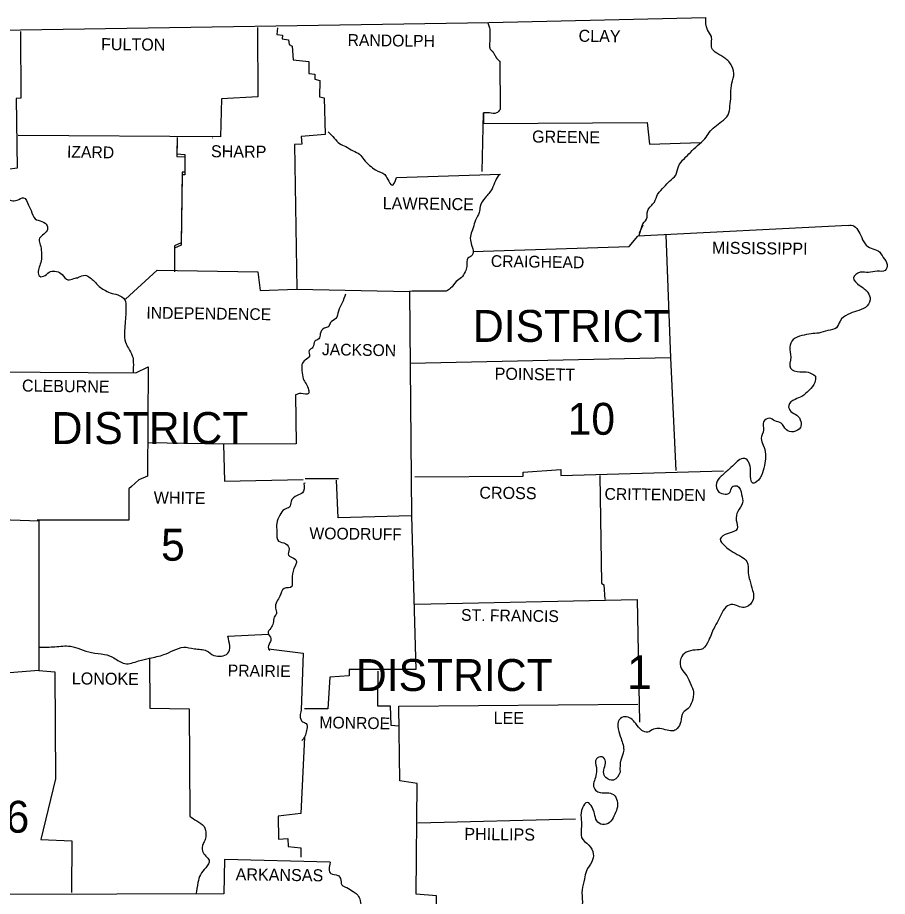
# Model space of a CAD drawing. Extents: x 1334737.7 to 1334827.2, y 402732.3 to 402753.5.
# Drawn here: x 1334823.697 to 1334827.213, y 402749.977 to 402753.53 of the extents above; entities that cross this region are included whole.
import ezdxf

# ---------------------------------------------------------------- set-up
doc = ezdxf.new("R2010")
doc.units = 0
doc.layers.add('Default', color=7, linetype='Continuous')

msp = doc.modelspace()

# ---------------------------------------------------------------- linework, layer by layer
at = {"layer": 'Default'}
for p, q in [((1334825.6459, 402753.3538), (1334825.6479, 402753.1584)), ((1334826.2084, 402752.6464), (1334826.2217, 402752.6885)), ((1334826.2114, 402752.6597), (1334826.2258, 402752.6926)), ((1334824.8603, 402751.6664), (1334824.995, 402751.6664))]:
    msp.add_line(p, q, dxfattribs=at)
for points in [[(1334820.2741, 402753.4772), (1334822.1034, 402753.4762), (1334823.7086, 402753.4803), (1334825.6027, 402753.5091), (1334826.4798, 402753.5297)], [(1334824.6669, 402753.4895), (1334824.669, 402753.2099), (1334824.522, 402753.2016), (1334824.5178, 402753.0474), (1334823.6993, 402753.0525)], [(1334824.7482, 402753.4885), (1334824.7451, 402753.4618), (1334824.7677, 402753.4587), (1334824.7667, 402753.4443), (1334824.7924, 402753.4392), (1334824.7945, 402753.4207), (1334824.8068, 402753.4135), (1334824.8109, 402753.359), (1334824.8747, 402753.3518), (1334824.8747, 402753.3034), (1334824.8983, 402753.3003), (1334824.8983, 402753.2808), (1334824.9189, 402753.2757), (1334824.9178, 402753.2099), (1334824.9364, 402753.2057), (1334824.9405, 402753.0577), (1334824.8438, 402753.0494), (1334824.8459, 402753.0176), (1334824.816, 402753.0165), (1334824.8263, 402752.4325), (1334825.2819, 402752.4222), (1334825.2901, 402751.5152), (1334824.9929, 402751.507), (1334824.9867, 402751.6602)], [(1334823.7086, 402753.4731), (1334823.7106, 402753.2037), (1334823.6921, 402753.2027), (1334823.6952, 402752.9209), (1334823.616, 402752.9096), (1334823.6222, 402752.8335), (1334823.65, 402752.7985), (1334823.6479, 402752.7101), (1334823.4937, 402752.7039), (1334823.4885, 402752.5661), (1334823.3477, 402752.561), (1334823.3415, 402752.3944), (1334823.3487, 402752.38), (1334823.3528, 402752.1137), (1334823.5944, 402752.0972), (1334823.5914, 402751.5019), (1334823.7836, 402751.4957), (1334823.7836, 402750.89), (1334823.6315, 402750.8787), (1334823.6201, 402750.745), (1334823.3662, 402750.744)], [(1334825.5749, 402752.9075), (1334825.5811, 402753.144), (1334825.5811, 402753.1019), (1334826.2423, 402753.105), (1334826.2515, 402753.0176), (1334826.4588, 402753.0244)], [(1334824.343, 402753.0443), (1334824.341, 402752.9785), (1334824.3729, 402752.9764), (1334824.3739, 402752.9045), (1334824.3626, 402752.9045), (1334824.3585, 402752.6196), (1334824.3317, 402752.6073), (1334824.3317, 402752.5127)], [(1334824.343, 402753.034), (1334824.341, 402752.9682), (1334824.3729, 402752.9662), (1334824.3739, 402752.8942), (1334824.3626, 402752.8942), (1334824.3585, 402752.6093), (1334824.3317, 402752.598), (1334824.3317, 402752.5024)], [(1334824.4849, 402753.0422), (1334824.486, 402753.0433)], [(1334825.2284, 402752.8829), (1334825.649, 402752.8973)], [(1334827.0546, 402752.6895), (1334826.2049, 402752.6458)], [(1334825.5376, 402752.5835), (1334826.1693, 402752.6042), (1334826.2049, 402752.6458)], [(1334826.3171, 402752.6516), (1334826.3359, 402752.1548), (1334826.3585, 402751.6993)], [(1334824.1333, 402752.3913), (1334824.2618, 402752.5086), (1334824.669, 402752.5024), (1334824.6772, 402752.4263), (1334824.8253, 402752.4325)], [(1334825.4299, 402752.4242), (1334825.2921, 402752.4242), (1334825.2819, 402752.4222)], [(1334826.3359, 402752.1548), (1334825.2845, 402752.131)], [(1334823.5944, 402752.0972), (1334824.1754, 402752.0942), (1334824.2258, 402752.1178), (1334824.2227, 402751.6756), (1334824.1878, 402751.6613), (1334824.1579, 402751.6345), (1334824.1477, 402751.6253), (1334824.1466, 402751.4978), (1334823.7764, 402751.4978)], [(1334824.8202, 402752.0047), (1334824.8232, 402751.8062), (1334824.5292, 402751.8052), (1334824.2268, 402751.8104)], [(1334824.5292, 402751.8052), (1334824.5333, 402751.6561), (1334824.851, 402751.6623)], [(1334825.3035, 402751.6736), (1334825.7405, 402751.6756), (1334825.7415, 402751.6921), (1334825.8927, 402751.7024), (1334825.8927, 402751.6787), (1334826.5508, 402751.6972)], [(1334826.051, 402751.6787), (1334826.0572, 402751.2438), (1334826.0675, 402751.2366), (1334826.0706, 402751.178)], [(1334824.8603, 402751.6479), (1334824.8541, 402751.6469)], [(1334825.2901, 402751.5152), (1334825.3065, 402750.8952), (1334825.0382, 402750.8941), (1334825.0371, 402750.8695), (1334824.959, 402750.8643), (1334824.9518, 402750.7358), (1334824.8572, 402750.7358)], [(1334825.3035, 402751.1584), (1334826.2012, 402751.1769)], [(1334826.2012, 402751.1769), (1334826.2104, 402750.6813)], [(1334824.5466, 402751.0299), (1334824.7112, 402751.0381)], [(1334824.7112, 402750.9785), (1334824.852, 402750.961), (1334824.8438, 402750.7296)], [(1334824.2299, 402750.9415), (1334824.232, 402750.7389), (1334824.3914, 402750.7358), (1334824.3934, 402750.3019)], [(1334823.7836, 402750.89), (1334823.8484, 402750.8849), (1334823.8505, 402750.453), (1334823.7908, 402750.2073), (1334823.9163, 402750.2021), (1334823.9153, 402749.9934)], [(1334825.1533, 402750.888), (1334825.1523, 402750.7481), (1334825.2037, 402750.7481), (1334825.2058, 402750.67), (1334825.2387, 402750.6669)], [(1334825.3035, 402749.7445), (1334825.3919, 402749.7507), (1334825.3909, 402749.98), (1334825.3086, 402749.9862), (1334825.3127, 402750.4345), (1334825.2418, 402750.4448), (1334825.2387, 402750.7471), (1334826.2042, 402750.7543)], [(1334824.8572, 402750.6217), (1334824.8428, 402750.3121), (1334824.7502, 402750.3019), (1334824.7523, 402750.2093), (1334824.7903, 402750.2114), (1334824.7914, 402750.1795), (1334824.8418, 402750.1733), (1334824.8428, 402750.1363)], [(1334825.3148, 402750.2751), (1334825.9523, 402750.2916)], [(1334824.961, 402750.1157), (1334824.5333, 402750.127), (1334824.5312, 402749.9882), (1334823.6654, 402749.9851)]]:
    msp.add_lwpolyline(points, dxfattribs=at)
for points in [[(1334826.2207, 402752.6834), (1334826.2217, 402752.6885), (1334826.2392, 402752.7152), (1334826.2443, 402752.7492), (1334826.2711, 402752.7841), (1334826.2844, 402752.815), (1334826.3112, 402752.8458), (1334826.3317, 402752.8685), (1334826.3575, 402752.8931), (1334826.3688, 402752.9281), (1334826.3924, 402752.96), (1334826.4171, 402752.9847), (1334826.4459, 402753.0124), (1334826.4757, 402753.0402), (1334826.4922, 402753.0649), (1334826.5158, 402753.0885), (1334826.5425, 402753.1091), (1334826.5693, 402753.1368), (1334826.5765, 402753.1718), (1334826.5806, 402753.2109), (1334826.5826, 402753.2551), (1334826.5919, 402753.2942), (1334826.5847, 402753.3332), (1334826.5559, 402753.3662), (1334826.523, 402753.3857), (1334826.5035, 402753.4063), (1334826.5014, 402753.4536), (1334826.486, 402753.4803), (1334826.4798, 402753.5297)], [(1334825.5966, 402753.509), (1334825.5992, 402753.5039), (1334825.6047, 402753.4879), (1334825.6064, 402753.477), (1334825.6067, 402753.4715), (1334825.6068, 402753.4659), (1334825.6066, 402753.4584), (1334825.6063, 402753.451), (1334825.606, 402753.4435), (1334825.6058, 402753.4361), (1334825.6057, 402753.4325), (1334825.6052, 402753.4217), (1334825.6052, 402753.4145), (1334825.6054, 402753.4109), (1334825.6055, 402753.4091), (1334825.6056, 402753.4082), (1334825.6058, 402753.4073), (1334825.6079, 402753.402), (1334825.6118, 402753.3975), (1334825.6163, 402753.3933), (1334825.6184, 402753.3911), (1334825.6202, 402753.3888), (1334825.6238, 402753.3827), (1334825.6271, 402753.3764), (1334825.6306, 402753.3701), (1334825.6325, 402753.3671), (1334825.6346, 402753.3641), (1334825.637, 402753.3612), (1334825.6397, 402753.3586), (1334825.6427, 402753.3562), (1334825.6459, 402753.3538)], [(1334825.6479, 402753.1584), (1334825.6325, 402753.144), (1334825.6047, 402753.144), (1334825.5811, 402753.144)], [(1334824.9528, 402753.068), (1334824.9775, 402753.0422), (1334824.9991, 402753.0206), (1334825.0238, 402753.0083), (1334825.0536, 402752.9908), (1334825.0793, 402752.9775), (1334825.0968, 402752.9559), (1334825.1204, 402752.9322), (1334825.1441, 402752.9137), (1334825.1811, 402752.8952), (1334825.1934, 402752.8757), (1334825.2109, 402752.852), (1334825.2284, 402752.8829)], [(1334825.6448, 402752.8962), (1334825.6284, 402752.8695), (1334825.615, 402752.8376), (1334825.5873, 402752.8016), (1334825.5667, 402752.7656), (1334825.5636, 402752.742), (1334825.5482, 402752.7111), (1334825.5389, 402752.6793), (1334825.5287, 402752.6515), (1334825.5287, 402752.6237), (1334825.5369, 402752.5949), (1334825.5348, 402752.5692), (1334825.5173, 402752.5569), (1334825.5132, 402752.524), (1334825.506, 402752.5014), (1334825.4916, 402752.4787), (1334825.47, 402752.4623), (1334825.4474, 402752.4356), (1334825.4299, 402752.4242)], [(1334823.65, 402752.7985), (1334823.6952, 402752.7913), (1334823.7219, 402752.8016), (1334823.7415, 402752.7718), (1334823.7518, 402752.7492), (1334823.7682, 402752.7163), (1334823.796, 402752.706), (1334823.8166, 402752.6885), (1334823.8166, 402752.669), (1334823.798, 402752.6505), (1334823.7847, 402752.633), (1334823.7888, 402752.6114), (1334823.7939, 402752.5816), (1334823.7939, 402752.5538), (1334823.7867, 402752.5271), (1334823.7806, 402752.5034), (1334823.7867, 402752.4839), (1334823.8083, 402752.487), (1334823.8309, 402752.5034), (1334823.8546, 402752.5034), (1334823.8772, 402752.4911), (1334823.9009, 402752.4695), (1334823.9245, 402752.4746), (1334823.9441, 402752.4798), (1334823.9708, 402752.488), (1334823.9903, 402752.4777), (1334824.0068, 402752.4643), (1334824.0273, 402752.4428), (1334824.0469, 402752.4294), (1334824.0716, 402752.417), (1334824.1024, 402752.4088), (1334824.1302, 402752.3893), (1334824.1353, 402752.3564), (1334824.1343, 402752.3286), (1334824.1322, 402752.2936), (1334824.1292, 402752.2546), (1334824.1333, 402752.2176), (1334824.1456, 402752.1929), (1334824.161, 402752.1631), (1334824.1651, 402752.1363), (1334824.1641, 402752.0931)], [(1334827.0546, 402752.6895), (1334827.067, 402752.6906), (1334827.105, 402752.6494), (1334827.1225, 402752.6155), (1334827.1472, 402752.597), (1334827.176, 402752.5867), (1334827.1965, 402752.56), (1334827.212, 402752.5322), (1334827.2037, 402752.5075), (1334827.1719, 402752.5044), (1334827.1369, 402752.4993), (1334827.103, 402752.5003), (1334827.0762, 402752.4777), (1334827.1009, 402752.4469), (1334827.1338, 402752.4191), (1334827.1431, 402752.3883), (1334827.1246, 402752.3584), (1334827.0886, 402752.343), (1334827.0536, 402752.3296), (1334827.0217, 402752.3029), (1334827.0073, 402752.2762), (1334826.9724, 402752.2649), (1334826.9354, 402752.2546), (1334826.9045, 402752.2515), (1334826.8675, 402752.2443), (1334826.8325, 402752.2278), (1334826.8181, 402752.198), (1334826.8222, 402752.1569), (1334826.8212, 402752.1127), (1334826.8593, 402752.0972), (1334826.8922, 402752.0962), (1334826.923, 402752.0798)], [(1334825.0227, 402752.4119), (1334825.0094, 402752.3769), (1334824.9939, 402752.343), (1334824.9837, 402752.3132), (1334824.9621, 402752.2967), (1334824.9549, 402752.2813), (1334824.9364, 402752.2741), (1334824.9209, 402752.2515), (1334824.9148, 402752.2309), (1334824.8983, 402752.2217), (1334824.8911, 402752.197), (1334824.8757, 402752.1836), (1334824.8767, 402752.161), (1334824.8603, 402752.1456), (1334824.8469, 402752.1271), (1334824.8469, 402752.1024), (1334824.852, 402752.0695), (1334824.8633, 402752.0499), (1334824.8736, 402752.0253), (1334824.8726, 402752.0098), (1334824.8438, 402752.0098), (1334824.8202, 402752.0047)], [(1334826.923, 402752.0798), (1334826.9199, 402752.0551), (1334826.8963, 402752.0232), (1334826.8675, 402751.9985), (1334826.8397, 402751.9862), (1334826.814, 402751.9615), (1334826.8222, 402751.9379), (1334826.8469, 402751.9224), (1334826.8634, 402751.8967), (1334826.8613, 402751.8731), (1334826.8335, 402751.8556), (1334826.8048, 402751.8628), (1334826.7832, 402751.8906), (1334826.7585, 402751.8998), (1334826.7369, 402751.9101), (1334826.7122, 402751.8957), (1334826.7122, 402751.8628), (1334826.703, 402751.8278), (1334826.7112, 402751.8011), (1334826.7204, 402751.7651), (1334826.7194, 402751.7384), (1334826.7112, 402751.6993), (1334826.6916, 402751.6602), (1334826.669, 402751.6479), (1334826.6598, 402751.69), (1334826.6557, 402751.725), (1334826.6413, 402751.7456), (1334826.6238, 402751.7466), (1334826.6001, 402751.7301), (1334826.5734, 402751.7044), (1334826.5405, 402751.6756), (1334826.522, 402751.6479), (1334826.5323, 402751.6119), (1334826.5569, 402751.6037), (1334826.5765, 402751.6098), (1334826.5857, 402751.6325), (1334826.6053, 402751.6366), (1334826.6238, 402751.6016)], [(1334824.8541, 402751.6469), (1334824.849, 402751.6088), (1334824.8274, 402751.5985), (1334824.8027, 402751.5738), (1334824.7965, 402751.5512), (1334824.7759, 402751.542), (1334824.7574, 402751.5183), (1334824.7451, 402751.4854), (1334824.7451, 402751.4515), (1334824.7523, 402751.4134), (1334824.7811, 402751.4032), (1334824.7945, 402751.3805), (1334824.7924, 402751.3569), (1334824.8191, 402751.3404), (1334824.8243, 402751.3271), (1334824.8191, 402751.3127), (1334824.8068, 402751.2705), (1334824.8078, 402751.2427), (1334824.8058, 402751.2304), (1334824.7749, 402751.2222), (1334824.7574, 402751.1913), (1334824.7451, 402751.1697), (1334824.74, 402751.142), (1334824.7441, 402751.1214), (1334824.7348, 402751.106), (1334824.7307, 402751.0823), (1334824.7204, 402751.0618), (1334824.7101, 402751.0422), (1334824.7214, 402751.0196), (1334824.7173, 402751.0042), (1334824.7112, 402750.9785), (1334824.7163, 402750.9713)], [(1334826.6238, 402751.6016), (1334826.6279, 402751.5687), (1334826.6084, 402751.5337), (1334826.6022, 402751.4978), (1334826.6053, 402751.4628), (1334826.5693, 402751.4443), (1334826.5374, 402751.4217), (1334826.5559, 402751.3939), (1334826.5898, 402751.3692), (1334826.6238, 402751.3497), (1334826.6454, 402751.3312), (1334826.6505, 402751.2849), (1334826.6567, 402751.2551), (1334826.668, 402751.2139), (1334826.6721, 402751.1862), (1334826.6515, 402751.1523), (1334826.6279, 402751.1451), (1334826.6032, 402751.1533), (1334826.5734, 402751.1553), (1334826.5497, 402751.1327), (1334826.5333, 402751.1008), (1334826.5158, 402751.069), (1334826.5035, 402751.0422), (1334826.4911, 402751.0134), (1334826.4664, 402750.9785), (1334826.4356, 402750.9733), (1334826.3996, 402750.9641), (1334826.378, 402750.9394), (1334826.3811, 402750.8972), (1334826.4017, 402750.8695), (1334826.4181, 402750.8345), (1334826.4294, 402750.8037), (1334826.4233, 402750.7656), (1334826.4078, 402750.7368), (1334826.3873, 402750.7204), (1334826.378, 402750.6834), (1334826.3636, 402750.6566), (1334826.3503, 402750.6474), (1334826.3225, 402750.6494), (1334826.2937, 402750.6556), (1334826.268, 402750.6535), (1334826.2443, 402750.6412), (1334826.2207, 402750.6484), (1334826.196, 402750.6762), (1334826.1754, 402750.6967), (1334826.1528, 402750.7039), (1334826.1292, 402750.6916), (1334826.1251, 402750.6546), (1334826.1364, 402750.6155), (1334826.1467, 402750.5641), (1334826.1364, 402750.5322), (1334826.1323, 402750.4797)], [(1334823.7857, 402750.9846), (1334823.8484, 402750.9867), (1334823.9112, 402750.9888), (1334823.9513, 402750.9774), (1334823.9965, 402750.963), (1334824.0489, 402750.9558), (1334824.087, 402750.9415), (1334824.1302, 402750.9188), (1334824.1867, 402750.9291), (1334824.231, 402750.9404), (1334824.2885, 402750.9548), (1334824.3266, 402750.9713), (1334824.3687, 402750.9846), (1334824.4119, 402750.9785), (1334824.4613, 402750.9702), (1334824.4911, 402750.9517), (1334824.5466, 402750.96), (1334824.5466, 402751.0299)], [(1334824.8438, 402750.7296), (1334824.8397, 402750.707), (1334824.849, 402750.6834), (1334824.8644, 402750.6762), (1334824.8664, 402750.6535), (1334824.8613, 402750.6309), (1334824.8572, 402750.6217), (1334824.8469, 402750.6083)], [(1334826.1323, 402750.4797), (1334826.1065, 402750.4479), (1334826.0685, 402750.4674), (1334826.0685, 402750.4952), (1334826.0736, 402750.5229), (1334826.0603, 402750.5414), (1334826.0366, 402750.5332), (1334826.0366, 402750.4983), (1334826.0346, 402750.4643), (1334826.0274, 402750.416), (1334826.0428, 402750.4006), (1334826.0798, 402750.3965), (1334826.1055, 402750.3893), (1334826.1209, 402750.3636), (1334826.1199, 402750.3317), (1334826.1076, 402750.3019), (1334826.0901, 402750.2761), (1334826.0613, 402750.2679), (1334826.0387, 402750.2823), (1334826.0294, 402750.3121), (1334826.0191, 402750.3378), (1334826.0006, 402750.3574), (1334825.9801, 402750.3358), (1334825.9749, 402750.2957), (1334825.977, 402750.2618), (1334825.977, 402750.2155), (1334826.0058, 402750.1846), (1334826.0243, 402750.1497), (1334826.0181, 402750.1178), (1334825.9965, 402750.0808), (1334825.9883, 402750.0479), (1334825.979, 402750.0037), (1334825.9801, 402749.9553), (1334825.9718, 402749.908), (1334825.9564, 402749.8761), (1334825.9266, 402749.8504), (1334825.9071, 402749.833), (1334825.8916, 402749.8165), (1334825.8834, 402749.7826), (1334825.8783, 402749.7589), (1334825.8567, 402749.7301), (1334825.8392, 402749.7281), (1334825.8258, 402749.7394), (1334825.8217, 402749.7589), (1334825.8217, 402749.7774), (1334825.8125, 402749.797), (1334825.7847, 402749.8052), (1334825.7621, 402749.8042), (1334825.7518, 402749.7877), (1334825.7662, 402749.7435), (1334825.7713, 402749.7157), (1334825.7641, 402749.6767), (1334825.7682, 402749.6725), (1334825.7281, 402749.6509), (1334825.6952, 402749.6479), (1334825.6675, 402749.6396), (1334825.6418, 402749.6232), (1334825.6294, 402749.5975), (1334825.6109, 402749.5779), (1334825.5955, 402749.5584), (1334825.5739, 402749.5491)], [(1334824.3934, 402750.3019), (1334824.4212, 402750.2823), (1334824.451, 402750.2597), (1334824.4582, 402750.2288), (1334824.4561, 402750.2073), (1334824.4469, 402750.1898), (1334824.4448, 402750.161), (1334824.4582, 402750.1404), (1334824.4716, 402750.124), (1334824.4582, 402750.0931), (1334824.4366, 402750.0653), (1334824.4263, 402750.0335), (1334824.4181, 402749.9862)], [(1334824.961, 402750.1157), (1334824.9641, 402750.0695), (1334824.9919, 402750.0623), (1334825.0022, 402750.0499), (1334825.0083, 402750.0242), (1334825.0279, 402750.0129), (1334825.0536, 402749.9975), (1334825.069, 402749.9862), (1334825.0803, 402749.9677), (1334825.0875, 402749.9378), (1334825.106, 402749.9193), (1334825.1307, 402749.9101), (1334825.1482, 402749.8885), (1334825.1595, 402749.8576), (1334825.178, 402749.8443), (1334825.1965, 402749.8206), (1334825.2047, 402749.8103), (1334825.2212, 402749.7836), (1334825.2366, 402749.7702), (1334825.2479, 402749.762), (1334825.2664, 402749.7558), (1334825.2891, 402749.7414), (1334825.3035, 402749.7188), (1334825.3035, 402749.7024), (1334825.2983, 402749.6756), (1334825.2932, 402749.6489), (1334825.2911, 402749.618), (1334825.2891, 402749.5913), (1334825.2993, 402749.5687), (1334825.2932, 402749.5348), (1334825.2819, 402749.5162), (1334825.2808, 402749.4916), (1334825.2777, 402749.4545), (1334825.2726, 402749.433), (1334825.2634, 402749.398), (1334825.2479, 402749.3795)]]:
    msp.add_spline(points, degree=3, dxfattribs=at)

# ---------------------------------------------------------------- texts
for s, height, rotation, p in [('FULTON', 0.04863, 359.4996, (1334824.0345, 402753.398)), ('RANDOLPH', 0.04751, 359.2583, (1334825.031, 402753.4155)), ('CLAY', 0.04863, 359.2258, (1334825.9646, 402753.432)), ('GREENE', 0.04864, 359.2361, (1334825.7765, 402753.0248)), ('IZARD', 0.04749, 358.9258, (1334823.8968, 402752.9641)), ('SHARP', 0.04863, 359.3905, (1334824.4788, 402752.9651)), ('LAWRENCE', 0.04864, 359.2678, (1334825.1729, 402752.7554)), ('MISSISSIPPI', 0.04863, 359.3097, (1334826.5035, 402752.5754)), ('CRAIGHEAD', 0.04751, 359.1159, (1334825.6099, 402752.5219)), ('INDEPENDENCE', 0.047495, 359.2187, (1334824.2176, 402752.3132)), ('JACKSON', 0.04749, 359.1352, (1334824.9271, 402752.1651)), ('POINSETT', 0.04863, 359.1987, (1334825.6253, 402752.0664)), ('CLEBURNE', 0.04863, 359.2535, (1334823.7148, 402752.0181)), ('WHITE', 0.04864, 359.3139, (1334824.2474, 402751.5656)), ('CROSS', 0.04863, 359.3839, (1334825.5636, 402751.5852)), ('CRITTENDEN', 0.04751, 359.213, (1334826.0695, 402751.581)), ('WOODRUFF', 0.04749, 359.2748, (1334824.8767, 402751.4217)), ('ST. FRANCIS', 0.047495, 359.2216, (1334825.4896, 402751.0916)), ('PRAIRIE', 0.04751, 359.2116, (1334824.5466, 402750.8674)), ('LONOKE', 0.04864, 359.4974, (1334823.9163, 402750.8345)), ('LEE', 0.04864, 359.4327, (1334825.6212, 402750.6751)), ('MONROE', 0.04749, 359.0331, (1334824.9168, 402750.6576)), ('PHILLIPS', 0.04863, 359.3179, (1334825.5029, 402750.2062)), ('ARKANSAS', 0.04863, 359.2678, (1334824.5785, 402750.0427))]:
    msp.add_text(s, height=height, rotation=rotation, dxfattribs=at).set_placement(p)
for s, height, p in [('DISTRICT', 0.12895, (1334825.538, 402752.2188)), ('10', 0.12895, (1334825.9205, 402751.8434)), ('DISTRICT', 0.12895, (1334823.8351, 402751.8062)), ('5', 0.1289, (1334824.2772, 402751.3343)), ('DISTRICT', 0.12895, (1334825.0649, 402750.8078)), ('1', 0.1357, (1334826.16, 402750.816)), ('DISTRICT 6', 0.12895, (1334822.8057, 402750.235))]:
    msp.add_text(s, height=height, dxfattribs=at).set_placement(p)

doc.saveas('drawing.dxf')
